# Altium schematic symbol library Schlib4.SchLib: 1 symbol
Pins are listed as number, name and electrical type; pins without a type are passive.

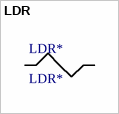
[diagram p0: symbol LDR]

## LDR
designator LDR*, comment LDR*
footprint PCBComponent_1
pins: 1, 2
